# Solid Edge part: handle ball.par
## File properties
Title: Handle Ball
Author: Deepak Maini
Template: Normal.par
Last saved by: Robert a Rhodes jr
Revision: 9
Application: Solid Edge
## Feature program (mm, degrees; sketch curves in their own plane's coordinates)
sketch for "unnamed RevolvedProtrusion 1" plane through (0, 0, 0) normal (0, -1, 0) x-axis (1, 0, 0)
  arc centre (0, 0) radius 9.525 from (0, 9.525) to (0, -9.525) cw
  line (0, 9.525) -> (0, -9.525)
revolve "unnamed RevolvedProtrusion 1" add finite 360 deg
sketch for "unnamed Cutout 1" plane through (0, 0, 0) normal (0, -1, 0) x-axis (1, 0, 0)
  circle centre (0, 0) radius 3.9751
extrude "unnamed Cutout 1" cut finite 50.8 symmetric
sketch for "unnamed Cutout 2" plane through (0, 0, 0) normal (0, 0, 1) x-axis (1, 0, 0)
  circle centre (0, 0) radius 1.905
extrude "unnamed Cutout 2" cut finite 50.8 symmetric
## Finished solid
Body 1: solid body, 4 faces, 6 edges, 0 vertices.
  Faces by surface: cylinder 3, sphere 1
  Edges by curve: circle 4, intersection 2
Bounding box of the edges (mm; curved faces can reach further): 7.950 x 17.312 x 18.665, from (-3.9751, -8.6559, -9.3326) to (3.9751, 8.6559, 9.3326).
Cylindrical faces by radius (mm): R1.905 x2, R3.9751 x1
Spherical faces by radius (mm): R9.525 x1
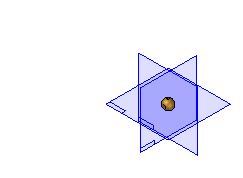
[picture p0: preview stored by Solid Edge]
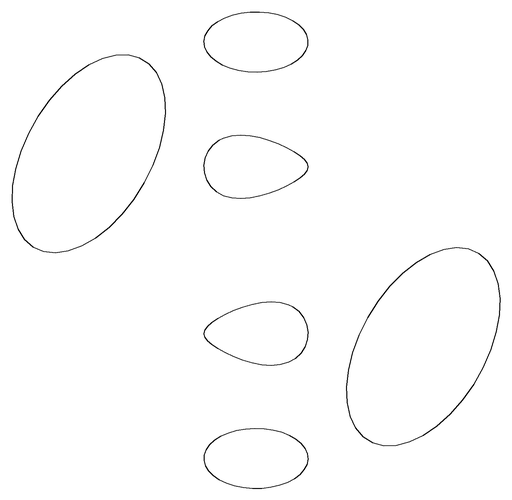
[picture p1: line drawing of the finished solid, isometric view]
